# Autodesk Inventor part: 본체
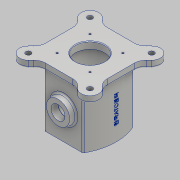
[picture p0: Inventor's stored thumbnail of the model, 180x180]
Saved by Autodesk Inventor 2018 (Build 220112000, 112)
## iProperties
Created: 2022-01
Part Number: 본체
Material: 알루미늄 6061
Document SubType Name: Modeling
Designer: home
Density: 2.7 g/cm^3
Appearance: 알루미늄 - 평지
Mass: 1228.11 g
Surface Area: 921.714 cm^2
Volume: 454.856 cm^3
Author: home
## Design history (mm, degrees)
sketch "스케치1"
  geometry: L1 (31.191, -45)-(-31.191, -45); A1 r 90 centre (45, 0) between (-37.506, 35.954) and (-33.818, -43.448); A2 r 90 centre (-45, 0) between (33.818, -43.448) and (37.506, 35.954); A3 r 90 centre (0, -45) between (35.954, 37.506) and (-35.954, 37.506); A4 r 3 centre (31.191, -42) between (31.191, -45) and (33.818, -43.448); A5 r 3 centre (-31.191, -42) between (-33.818, -43.448) and (-31.191, -45); A6 r 3 centre (-34.756, 34.756) between (-35.954, 37.506) and (-37.506, 35.954); A7 r 3 centre (34.756, 34.756) between (37.506, 35.954) and (35.954, 37.506); 3 further points
  constraints: 17 point on circle, 8 tangent, 7 centre point, 3 equal radius, 2 end point, 2 point on line, 1 midpoint
  dimensions: "d3" = 45 distance from line of point (0, 0) L1; "d11" = 90 distance edge to line of A3 L1; "d12" = 90 distance of A2.centre A1.centre; "d13" = 45 distance of A3.centre point (0, 0); "d16" = 45 distance of point (0, 0) A1.centre; "d17" = 45 distance of A2.centre point (0, 0); "d18" = 45 distance from line of L1 A2.centre; "d19" = 90 radius of A2; "d20" = 3 radius of A4; "d83" = 31.19055 horizontal distance of point (0, 0) A4.centre
extrude "돌출1" new body sketch "스케치1" stored distance "d21" = 98; taper "d22" = 0 deg
sketch "스케치2"
  geometry: L1 (-53, 53)-(53, 53); L2 (53, 53)-(53, -53); L3 (53, -53)-(-53, -53); L4 (-53, -53)-(-53, 53); L5 (-31.191, -45)-(31.191, -45) reference; A1 r 3 centre (31.191, -42) between (31.191, -45) and (33.818, -43.448) reference; A2 r 90 centre (-45, 0) between (33.818, -43.448) and (37.506, 35.954) reference; A3 r 3 centre (34.756, 34.756) between (37.506, 35.954) and (35.954, 37.506) reference; A4 r 90 centre (0, -45) between (35.954, 37.506) and (-35.954, 37.506) reference; A5 r 3 centre (-34.756, 34.756) between (-35.954, 37.506) and (-37.506, 35.954) reference; A6 r 90 centre (45, 0) between (-37.506, 35.954) and (-33.818, -43.448) reference; A7 r 3 centre (-31.191, -42) between (-33.818, -43.448) and (-31.191, -45) reference; 1 further point
  constraints: 8 end point, 2 parallel, 1 horizontal, 1 perpendicular
  dimensions: "d23" = 106 distance between parallel lines of L4 L2; "d24" = 53 distance from line of L2 point (0, 0); "d25" = 106 distance between parallel lines of L3 L1; "d26" = 53 distance from line of L3 point (0, 0)
extrude "돌출2" join sketch "스케치2" distance "d31" = 12; taper "d32" = 0 deg
sketch "스케치3" dims "d33" = 150
  geometry: L1 (0, 0)-(-113.388, 113.388); L2 (0, 0)-(-112.107, 0); L3 (-42.426, 63.64)-(-31.787, 53); L4 (-63.64, 42.426)-(-53, 31.787); L5 (-53, 53)-(-53, -53) reference; L6 (53, 53)-(-53, 53) reference; A1 r 15 centre (-53.033, 53.033) between (-42.426, 63.64) and (-63.64, 42.426); 2 further points
  constraints: 8 end point, 3 point on line, 2 coincident, 2 parallel, 2 point on circle, 1 centre point, 1 horizontal, 3 other
  dimensions: "d34" = 45 deg angle of L1 L2; "d36" = 15 distance between parallel lines of L3 L1; "d37" = 15 distance between parallel lines of L4 L1; "d38" = 15 radius of A1
extrude "돌출3" join sketch "스케치3" distance "d39" = 12; taper "d40" = 0 deg
fillet "모깎기1" dims "d44" = 20
sketch "스케치4"
  geometry: A1 r 15 centre (-53.033, 53.033) between (-42.426, 63.64) and (-63.64, 42.426) reference; 2 further points
  constraints: 1 coincident
hole "구멍1" sketch "스케치4" at (-53.033, 53.033) diameter "d45" = 9; stored, may be unused: countersink angle "d49" = 90 deg, drill point angle "d51" = 118 deg; dims "d46" = 6, "d47" = 18, "d48" = 2, "d50" = 8
sketch "스케치7"
  geometry: L1 (0, 0)-(0, 151.16); L2 (25, -49)-(25, -37); L3 (25, -37)-(37, -37); L4 (37, -37)-(37, 49); L5 (37, 49)-(25, 49); L6 (25, 49)-(25, 61); L7 (25, -49)-(0, -49); L8 (0, -49)-(0, 61); L9 (25, 61)-(0, 61)
  constraints: 18 end point, 3 perpendicular, 3 point on line, 2 vertical, 1 horizontal
  dimensions: "d58" = 50 diameter of L6 L1; "d59" = 74 diameter of L4 L1; "d60" = 86 distance of L3.end L4.end; "d61" = 12 distance between parallel lines of L9 L5; "d62" = 49 distance from line of L7 L1.start; "d63" = 61 distance from line of L9 L1.start
revolve "회전1" sketch "스케치7" stored, may be unused: angle "d64" = 90 deg
fillet "모깎기2" dims "d65" = 3
chamfer "모따기1" distance "d66" = 1; stored, may be unused: second distance "d67" = 2, angle "d68" = 45 deg
node "작업 평면3"
sketch "스케치10"
  geometry: L1 (23.503, 61)-(-23.503, 61) reference; C1 r 20 at (0, 0); 1 further point
  constraints: 1 centre point, 1 coincident
  dimensions: "d74" = 20 radius of C1
extrude "돌출4" join sketch "스케치10" stored distance "d76" = 12; taper "d77" = 10 deg
node "작업 평면4"
sketch "스케치11"
  geometry: 2 further points
  constraints: 1 coincident, 1 other
feature "엠보싱1" sketch "스케치11" dims "d80" = 0.5, "d81" = 0
sketch "스케치12"
  geometry: L1 (-32, -15)-(-42, -15); L2 (-42, -12)-(-42, -12); L3 (-43, -12)-(-55, -12); L4 (-55, 20)-(-55, -20) reference; L5 (-55, -12)-(-55, 0); L6 (-55, 0)-(-32, 0); L7 (0, 0)-(-30.068, 0); L8 (-42, -15)-(-42, -15); L9 (-42, -13)-(-42, -15); L10 (-42, -13)-(-43, -12); L11 (-32, -15)-(-32, 0); 1 further point
  constraints: 20 end point, 5 point on line, 3 perpendicular, 2 horizontal, 1 midpoint, 1 vertical
  dimensions: "d84" = 30 diameter of L1 L7; "d85" = 24 diameter of L3 L7; "d86" = 13 distance of L2.end L3.end; "d117" = 13 distance of point (-42, -12) L3.end; "d118" = 1 distance of L9.start point (-42, -12); "d119" = 1 distance of L3.start point (-42, -12) (= d118); "d120" = 23 distance between parallel lines of L11 L5; "d122" = 135 deg angle of L10 L4; "d123" = 24.93227 distance from line of L7.end L4
revolve "회전2" sketch "스케치12" stored, may be unused: angle "d87" = 90 deg
sketch "스케치13" dims "d89" = 40
  geometry: L1 (0, 0)-(73.114, 0); 2 further points
  constraints: 2 end point, 1 coincident, 1 horizontal, 3 other
  dimensions: "d90" = 45 deg dimension on L1.start L1.end point (28.284, -28.284)
hole "구멍2" sketch "스케치13" at (28.284, -28.284) diameter "d91" = 3.242; stored, may be unused: countersink angle "d95" = 90 deg, drill point angle "d97" = 118 deg; dims "d92" = 9, "d93" = 18, "d94" = 2, "d96" = 11
sketch "스케치14"
  geometry: L1 (0, 0)-(28.284, -28.284); L2 (23.503, 53)-(-23.503, 53) reference; C1 r 1.621 at (28.284, -28.284) reference; 1 further point
  constraints: 2 end point, 1 coincident
  dimensions: "d101" = 40 distance of L1.start L1.end; "d102" = 45 deg angle of L2 L1
hole "구멍3" sketch "스케치14" at (28.284, -28.284) diameter "d103" = 3.242; stored, may be unused: countersink angle "d107" = 90 deg, drill point angle "d109" = 118 deg; dims "d104" = 9, "d105" = 18, "d106" = 2, "d108" = 11
fillet "모깎기3" dims "d113" = 3
node "솔리드1"
pattern_circular "원형 패턴1" dims angle "d42" = 360 deg
pattern_circular "원형 패턴2" dims angle "d53" = 360 deg
pattern_circular "원형 패턴3" dims angle "d99" = 360 deg
pattern_circular "원형 패턴4" dims angle "d111" = 360 deg
node "투영된 루프1"
node "작업축1"
node "작업축2"
node "작업축3"
node "작업축4"
node "작업축5"
node "작업축6"
other parameters: "d35" = 15, "d73" = -55, "d79" = 78.5
